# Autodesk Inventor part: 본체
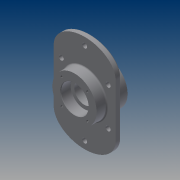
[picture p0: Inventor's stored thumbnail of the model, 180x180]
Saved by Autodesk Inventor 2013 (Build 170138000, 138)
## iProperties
Created: 2015-02
Part Number: 본체
Material: 일반
Document SubType Name: Modeling
Designer: cad8
Density: 1 g/cm^3
Author: cad8
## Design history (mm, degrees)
sketch "스케치1"
  geometry: L1 (0, 35)-(50, 35); L2 (50, 35)-(50, -35); L3 (50, -35)-(0, -35); L4 (0, -35)-(0, 35); L5 (31, 35)-(31, 13); L6 (31, 13)-(22.5, 13); L7 (22.5, 13)-(22.5, -13); L8 (22.5, -13)-(31, -13); L9 (31, -13)-(31, -35); 2 further points
  constraints: 18 end point, 5 parallel, 3 perpendicular, 2 point on line, 1 coincident, 1 horizontal, 1 midpoint
  dimensions: "d0" = 70 distance of L3.end L1.start; "d2" = 100 diameter of L2 L4; "d3" = 22 distance of L5.start L5.end; "d4" = 22 distance of L8.end L9.end; "d5" = 62 diameter of L5 L4; "d6" = 62 diameter of L9 L4; "d7" = 45 diameter of L7 L4
revolve "회전1" sketch "스케치1" stored, may be unused: angle "d8" = 90 deg
node "작업 평면1"
sketch "스케치2"
  geometry: L1 (-70, 60)-(-70, -60); L2 (70, -60)-(70, 60); C1 r 50 at (0, 0) reference; 5 further points; 2 other entities
  constraints: 4 end point, 1 coincident, 1 horizontal alignment, 1 midpoint, 1 parallel, 1 vertical alignment, 8 other
  dimensions: "d10" = 140 distance of L2.end L1.start; "d12" = 120 distance of L1.start L1.end; "d15" = 70 distance from line of L1 point (0, 0); "d16" = 70 distance of point (0, 0) point (70, 0)
extrude "돌출1" join sketch "스케치2" distance "d17" = 12; taper "d18" = 0 deg
sketch "스케치3"
  geometry: L1 (70, -60)-(70, 60) reference; L2 (-70, 60)-(-70, -60) reference; L3 (53, 60)-(53, -60); L4 (-53, -60)-(-53, 60); C1 r 50 at (0, 0) reference; C2 r 10 at (0, 93); 2 further points; 2 other entities
  constraints: 4 end point, 3 parallel, 1 centre point, 1 horizontal alignment, 1 vertical alignment, 8 other
  dimensions: "d19" = 17 distance between parallel lines of L4 L2; "d20" = 20 diameter of C2
extrude "돌출2" join sketch "스케치3" distance "d21" = 5; taper "d22" = 0 deg
sketch "스케치4"
  geometry: C1 r 10 at (0, 0) reference; C2 r 5.5 at (0, 0); 1 further point
  constraints: 1 centre point, 1 coincident
  dimensions: "d23" = 11 diameter of C2
extrude "돌출3" cut sketch "스케치4" stored distance "d25" = 5; taper "d26" = 0 deg
node "작업 평면2"
sketch "스케치6" dims "d31" = 82
  geometry: L1 (0, 0)-(0, 50); L2 (0, 0)-(35.355, 35.355); A1 r 50 centre (0, 0) between (0, 50) and (35.355, 35.355) reference; 2 further points
  constraints: 4 end point, 2 point on circle, 1 coincident, 1 point on line, 1 vertical, 3 other
  dimensions: "d30" = 45 deg angle of L2 L1
hole "구멍1" sketch "스케치6" at (28.991, 28.991) diameter "d33" = 4.917; stored, may be unused: countersink angle "d37" = 90 deg, drill point angle "d39" = 118 deg; dims "d34" = 10, "d35" = 4, "d36" = 2, "d38" = 13
fillet "모깎기1" dims "d43" = 0.3
chamfer "모따기1" distance "d44" = 1; stored, may be unused: second distance "d45" = 2, angle "d46" = 45 deg
node "작업 평면3"
sketch "스케치7"
  geometry: 2 further points
  constraints: 1 vertical alignment, 1 other
  dimensions: "d48" = 65 distance of point (0, -65) point (0, 0)
feature "엠보싱1" sketch "스케치7" dims "d0" = 70, "d2" = 100, "d3" = 22, "d4" = 22, "d5" = 62, "d6" = 62, "d7" = 45, "d49" = 1, "d50" = 0
fillet "모깎기2" dims "d51" = 3
node "솔리드1"
pattern_linear "직사각형 패턴1"
pattern_circular "원형 패턴1" dims angle "d41" = 360 deg
mirror "대칭1"
sketch "스케치5"
  geometry: L1 (70, -60)-(70, 60) reference; L2 (-70, 60)-(-70, -60) reference; L3 (53, 60)-(53, -60); L4 (-53, -60)-(-53, 60); C1 r 10 at (0, 93) reference; 2 further points; 2 other entities
  constraints: 4 end point, 3 parallel, 2 horizontal alignment, 6 other
  dimensions: "d27" = 17 distance between parallel lines of L4 L2
other parameters: "d9" = -23
